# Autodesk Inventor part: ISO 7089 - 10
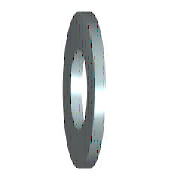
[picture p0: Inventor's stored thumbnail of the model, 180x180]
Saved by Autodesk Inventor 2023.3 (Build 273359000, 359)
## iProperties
Created: 2022-02
Part Number: ISO 7089 - 10
Material: Acier inoxydable
Description: Rondelles plates - Série standard - Produit de classe A
Document SubType Name: Modeling
Standard: ISO 7089
Designer: Thier
Standard Revision: Second edition 2000-06-01
Standards Organization: ISO
Language: fr-FR
Size Designation: 10
Categories: <MemberInstance><Categories><Category DisplayName="Visserie" InternalName="e4da775c-781d-43d5-af7c-5136215cf5a6" Mnemonic="FSTN"><Category DisplayName="Rondelle
Density: 8 g/cm^3
Appearance: Semi-poli
IsCustomPart: 0
Author: Thier
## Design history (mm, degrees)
sketch "Esquisse"
  geometry: C1 r 10 at (0, 0); C2 r 5.25 at (0, 0); 1 further point
  constraints: 2 centre point, 2 coincident
  dimensions: "d0" = 10.5 diameter of C2 (= SD1); "d1" = 20 diameter of C1 (= SD2)
extrude "Corps" new body sketch "Esquisse" distance "d2" = 2 (= SD); taper "d3" = 0 deg
workaxis "Work Axis1"
workplane "Work Plane1"
body "Solid1"
other parameters: "SD1" = 10.5 [user parameter; used in 1 equation term], "SD2" = 20 [user parameter; used in 1 equation term], "SD" = 2 [user parameter; used in 1 equation term], "d4" = 0, "d5" = 0, "d6" = 0, "d7" = 0
